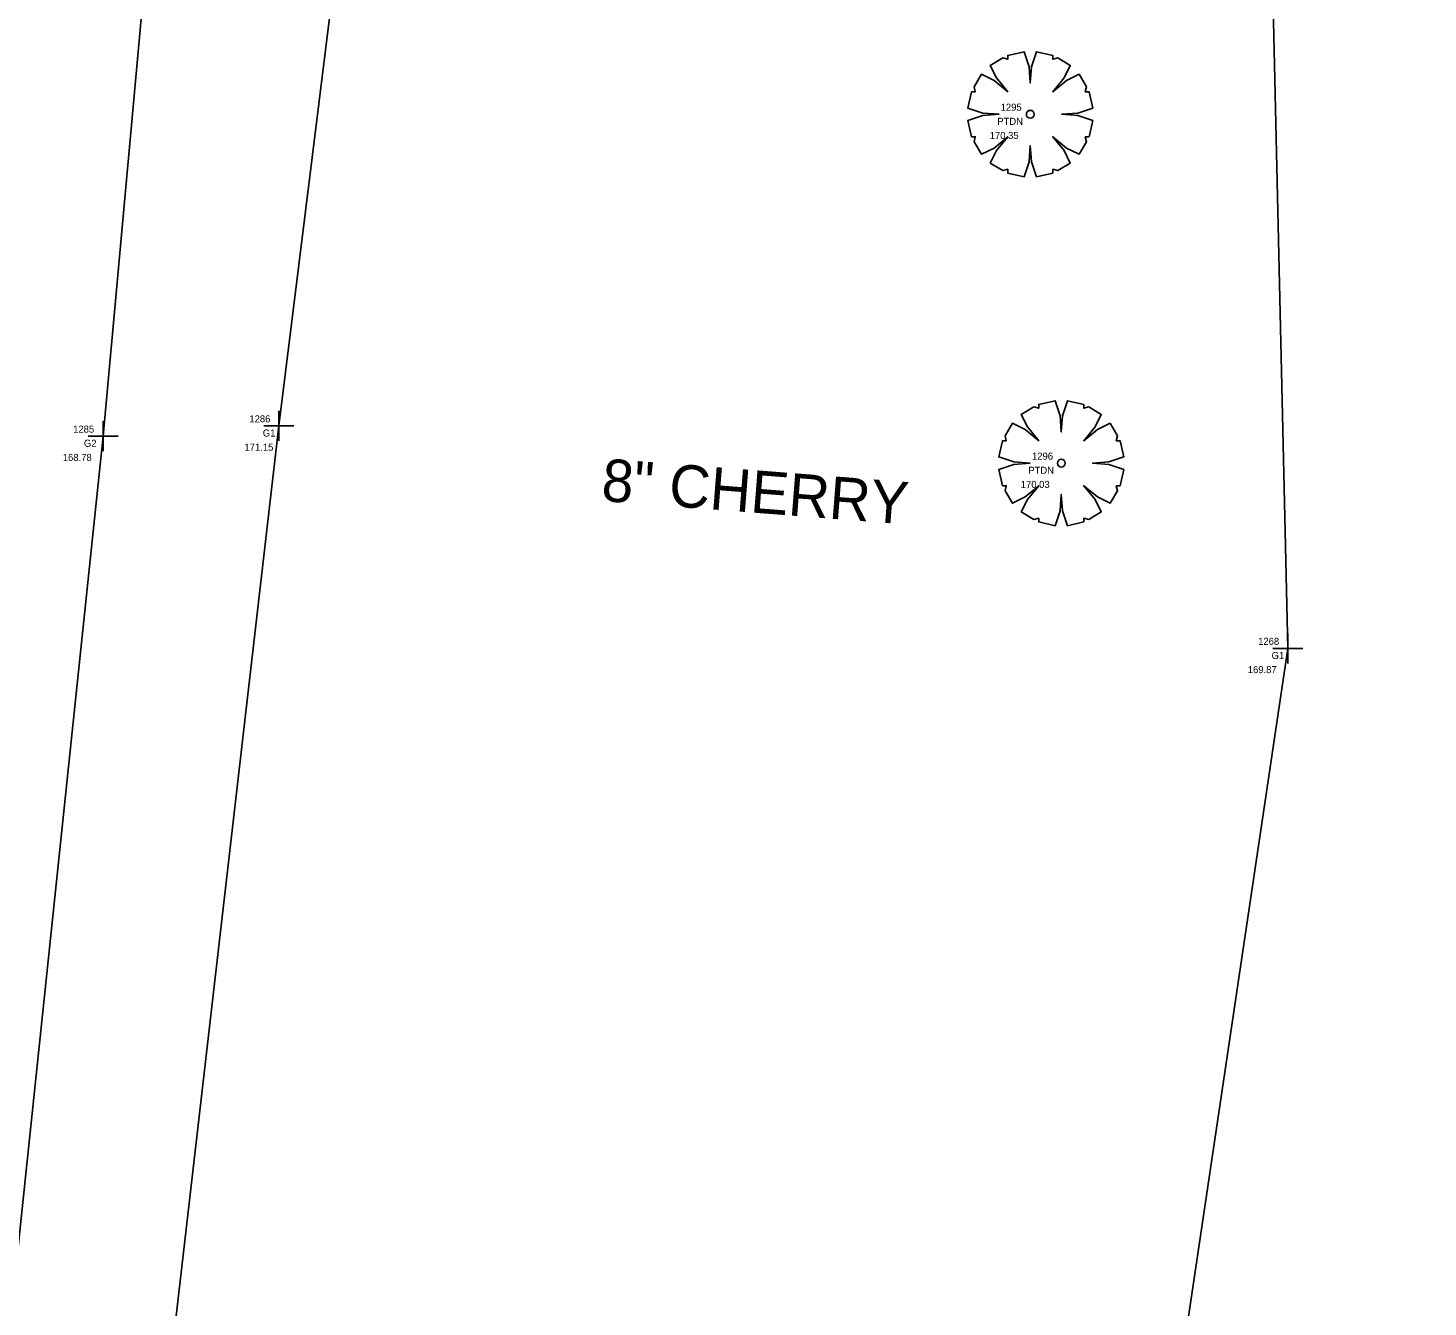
# Model space of a CAD drawing. Extents: x 1158391 to 1159969, y 606312 to 607106.
# Drawn here: x 1159244.7 to 1159304.1, y 606520.1 to 606574.4 of the extents above; entities that cross this region are included whole.
import ezdxf

# ---------------------------------------------------------------- set-up
doc = ezdxf.new("R2010")
doc.units = 0
for name, color, linetype in [('Default', 7, 'Continuous'), ('S_Field_Code', 7, 'Continuous'), ('S_Point_Elevation', 7, 'Continuous'), ('S_Point_Name', 7, 'Continuous'), ('S_Roadway_Centerline', 7, 'Continuous'), ('S_Terrain_High_Points', 7, 'Continuous'), ('S_Text', 7, 'Continuous'), ('Teal Point', 7, 'Continuous')]:
    doc.layers.add(name, color=color, linetype=linetype)

msp = doc.modelspace()

# ---------------------------------------------------------------- linework, layer by layer
at = {"layer": 'Default'}
for p, q in [((1159287.268, 606570.716), (1159287.268, 606570.716)), ((1159288.584, 606555.914), (1159288.584, 606555.914))]:
    msp.add_line(p, q, dxfattribs=at)
at = {"layer": 'S_Roadway_Centerline'}
for points in [[(1159285.942, 606570.716), (1159285.253, 606570.769), (1159284.617, 606570.981), (1159284.775, 606571.671), (1159284.935, 606571.671), (1159284.881, 606571.883), (1159285.199, 606572.414), (1159285.73, 606572.148), (1159286.314, 606571.671), (1159285.836, 606572.254), (1159285.571, 606572.785), (1159286.102, 606573.103), (1159286.314, 606573.05), (1159286.314, 606573.209), (1159287.003, 606573.368), (1159287.215, 606572.732), (1159287.269, 606572.042), (1159287.321, 606572.732), (1159287.533, 606573.368), (1159288.224, 606573.209), (1159288.224, 606573.05), (1159288.436, 606573.103), (1159288.966, 606572.785), (1159288.7, 606572.254), (1159288.224, 606571.671), (1159288.806, 606572.148), (1159289.337, 606572.414), (1159289.655, 606571.883), (1159289.603, 606571.671), (1159289.761, 606571.671), (1159289.921, 606570.981), (1159289.285, 606570.769), (1159288.594, 606570.716), (1159289.285, 606570.663), (1159289.921, 606570.451), (1159289.761, 606569.761), (1159289.603, 606569.761), (1159289.655, 606569.549), (1159289.337, 606569.019), (1159288.806, 606569.284), (1159288.224, 606569.761), (1159288.7, 606569.178), (1159288.966, 606568.647), (1159288.436, 606568.329), (1159288.224, 606568.382), (1159288.224, 606568.223), (1159287.533, 606568.064), (1159287.321, 606568.7), (1159287.269, 606569.39), (1159287.215, 606568.7), (1159287.003, 606568.064), (1159286.314, 606568.223), (1159286.314, 606568.382), (1159286.102, 606568.329), (1159285.571, 606568.647), (1159285.836, 606569.178), (1159286.314, 606569.761), (1159285.73, 606569.284), (1159285.199, 606569.019), (1159284.881, 606569.549), (1159284.935, 606569.761), (1159284.775, 606569.761), (1159284.617, 606570.451), (1159285.253, 606570.663), (1159285.942, 606570.716)], [(1159287.258, 606555.914), (1159286.569, 606555.967), (1159285.933, 606556.179), (1159286.091, 606556.869), (1159286.251, 606556.869), (1159286.197, 606557.081), (1159286.516, 606557.611), (1159287.046, 606557.346), (1159287.63, 606556.869), (1159287.152, 606557.452), (1159286.888, 606557.983), (1159287.418, 606558.301), (1159287.63, 606558.248), (1159287.63, 606558.407), (1159288.319, 606558.566), (1159288.531, 606557.93), (1159288.585, 606557.24), (1159288.637, 606557.93), (1159288.849, 606558.566), (1159289.54, 606558.407), (1159289.54, 606558.248), (1159289.752, 606558.301), (1159290.282, 606557.983), (1159290.016, 606557.452), (1159289.54, 606556.869), (1159290.123, 606557.346), (1159290.653, 606557.611), (1159290.971, 606557.081), (1159290.919, 606556.869), (1159291.077, 606556.869), (1159291.237, 606556.179), (1159290.601, 606555.967), (1159289.91, 606555.914), (1159290.601, 606555.861), (1159291.237, 606555.649), (1159291.077, 606554.959), (1159290.919, 606554.959), (1159290.971, 606554.747), (1159290.653, 606554.216), (1159290.123, 606554.482), (1159289.54, 606554.959), (1159290.016, 606554.376), (1159290.282, 606553.845), (1159289.752, 606553.527), (1159289.54, 606553.58), (1159289.54, 606553.421), (1159288.849, 606553.262), (1159288.637, 606553.898), (1159288.585, 606554.588), (1159288.531, 606553.898), (1159288.319, 606553.262), (1159287.63, 606553.421), (1159287.63, 606553.58), (1159287.418, 606553.527), (1159286.888, 606553.845), (1159287.152, 606554.376), (1159287.63, 606554.959), (1159287.046, 606554.482), (1159286.516, 606554.216), (1159286.197, 606554.747), (1159286.251, 606554.959), (1159286.091, 606554.959), (1159285.933, 606555.649), (1159286.569, 606555.861), (1159287.258, 606555.914)]]:
    msp.add_lwpolyline(points, dxfattribs=at)
for centre in [(1159287.268, 606570.716), (1159288.584, 606555.914)]:
    msp.add_circle(centre, 0.166, dxfattribs=at)
at = {"layer": 'S_Terrain_High_Points'}
for points in [[(1159243.119, 606451.5), (1159241.24, 606474.742), (1159243.969, 606519.295), (1159247.925, 606557.059), (1159251.39, 606595.115), (1159254.114, 606629.119), (1159255.647, 606654.267)], [(1159245.208, 606451.414), (1159245.807, 606475.77), (1159250.675, 606516.681), (1159255.387, 606557.495), (1159259.895, 606593.828), (1159259.161, 606617.811), (1159264.191, 606627.099), (1159262.652, 606637.377), (1159262.884, 606654.309)], [(1159304.145, 606645.216), (1159302.374, 606629.727), (1159301.994, 606615.955), (1159297.488, 606579.01), (1159298.193, 606548.058), (1159291.917, 606505.83), (1159285.688, 606454.146)]]:
    msp.add_lwpolyline(points, dxfattribs=at)
at = {"layer": 'Teal Point'}
for p, q in [((1159255.389, 606556.859), (1159255.386, 606558.132)), ((1159247.926, 606556.423), (1159247.924, 606557.695)), ((1159254.751, 606557.494), (1159256.024, 606557.497)), ((1159255.387, 606557.495), (1159255.387, 606557.495)), ((1159247.289, 606557.058), (1159248.561, 606557.06)), ((1159247.925, 606557.059), (1159247.925, 606557.059)), ((1159298.195, 606547.421), (1159298.192, 606548.694)), ((1159297.557, 606548.056), (1159298.83, 606548.059)), ((1159298.193, 606548.058), (1159298.193, 606548.058))]:
    msp.add_line(p, q, dxfattribs=at)

# ---------------------------------------------------------------- texts
at = {"layer": 'S_Field_Code'}
for s, p in [('PTDN', (1159285.868, 606570.266)), ('G2', (1159247.11, 606556.609)), ('G1', (1159254.702, 606557.045)), ('PTDN', (1159287.184, 606555.464)), ('G1', (1159297.509, 606547.608))]:
    msp.add_text(s, height=0.3, dxfattribs=at).set_placement(p)
at = {"layer": 'S_Point_Elevation'}
for s, p in [('170.35', (1159285.547, 606569.666)), ('168.78', (1159246.215, 606556.009)), ('171.15', (1159253.923, 606556.445)), ('170.03', (1159286.865, 606554.864)), ('169.87', (1159296.498, 606547.008))]:
    msp.add_text(s, height=0.3, dxfattribs=at).set_placement(p)
at = {"layer": 'S_Point_Name'}
for s, p in [('1295', (1159286.012, 606570.866)), ('1285', (1159246.654, 606557.209)), ('1286', (1159254.131, 606557.645)), ('1296', (1159287.342, 606556.064)), ('1268', (1159296.937, 606548.208))]:
    msp.add_text(s, height=0.3, dxfattribs=at).set_placement(p)
at = {"layer": 'S_Text'}
msp.add_text('8" CHERRY', height=1.8, rotation=355.55999, dxfattribs=at).set_placement((1159269.037, 606554.32))

doc.saveas('drawing.dxf')
